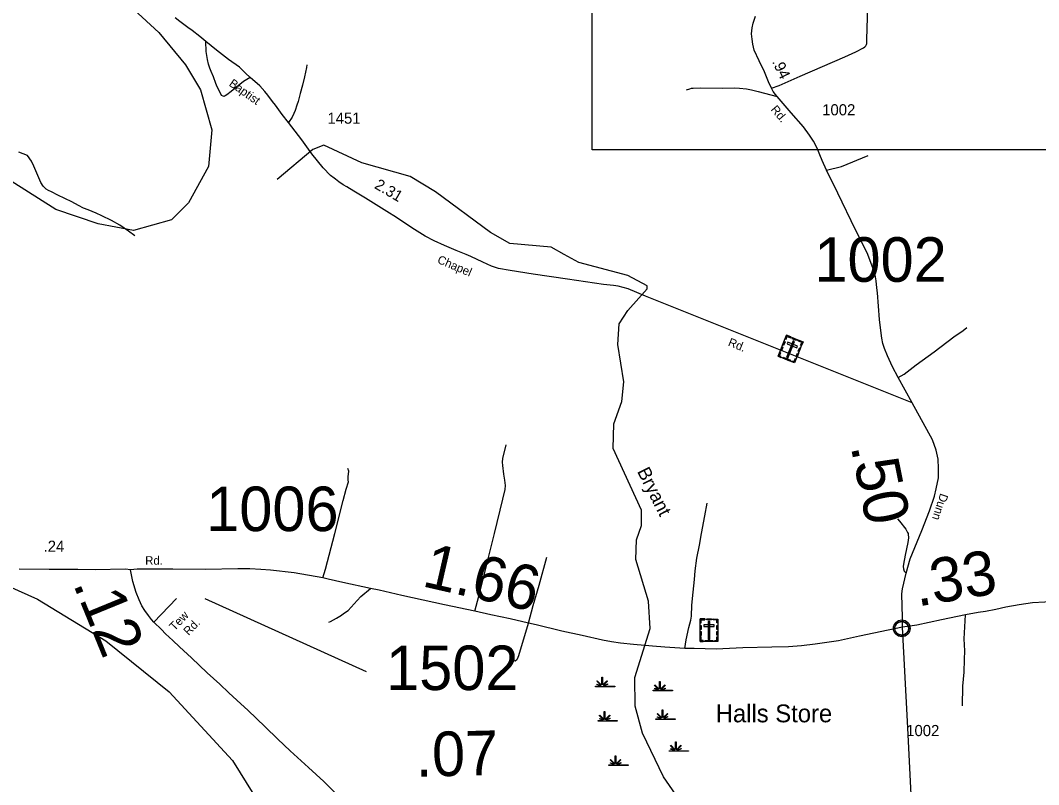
# Model space of a CAD drawing. Extents: x 2093524 to 2270757, y 289120 to 570408.
# Drawn here: x 2128353 to 2139794, y 494834 to 503417 of the extents above; entities that cross this region are included whole.
import ezdxf

# ---------------------------------------------------------------- set-up
doc = ezdxf.new("R2010")
doc.units = 0
for name, color, linetype in [('Exist Civil Demographics Community CELL', 7, 'Continuous'), ('Exist Civil Demographics Community Label', 7, 'Continuous'), ('Exist Cultural Cemetery CELL', 7, 'Continuous'), ('Exist Hydrographic Creek Single Shore', 7, 'Continuous'), ('Exist Hydrographic Misc Water Feature', 7, 'Continuous'), ('Exist Hydrographic Pond Under 1500 Sq Ft', 7, 'Continuous'), ('Exist Hydrographic Swamp CELL', 7, 'Continuous'), ('Exist Hydrographic Swamp Label', 7, 'Continuous'), ('Exist Road Non-System Type 51', 7, 'Continuous'), ('Exist Road Secondary Mileage Hundredths English Label', 7, 'Continuous'), ('Exist Road Secondary Type 51 Attributed', 7, 'Continuous'), ('Exist Road Secondary Type 51 Label', 7, 'Continuous'), ('Exist Road Secondary Type 51 Number Label', 7, 'Continuous'), ('Map Preparation Inset Cut Line', 7, 'Continuous')]:
    doc.layers.add(name, color=color, linetype=linetype)

msp = doc.modelspace()

# ---------------------------------------------------------------- linework, layer by layer
at = {"layer": 'Exist Civil Demographics Community CELL'}
msp.add_lwpolyline([(2138178, 496602), (2138179, 496607), (2138181, 496614), (2138184, 496621), (2138187, 496627), (2138190, 496632), (2138194, 496638), (2138198, 496642), (2138202, 496647), (2138208, 496651), (2138213, 496655), (2138218, 496658), (2138223, 496660), (2138229, 496662), (2138234, 496664), (2138239, 496665), (2138244, 496666), (2138248, 496667), (2138254, 496667), (2138258, 496667), (2138264, 496667), (2138269, 496666), (2138274, 496665), (2138279, 496664), (2138284, 496662), (2138291, 496659), (2138297, 496655), (2138302, 496652), (2138307, 496648), (2138311, 496645), (2138315, 496640), (2138319, 496635), (2138322, 496631), (2138325, 496626), (2138327, 496621), (2138329, 496616), (2138331, 496611), (2138332, 496606), (2138333, 496600), (2138334, 496595), (2138334, 496589), (2138334, 496584), (2138333, 496578), (2138332, 496572), (2138331, 496566), (2138329, 496560), (2138327, 496555), (2138323, 496549), (2138320, 496544), (2138317, 496539), (2138312, 496535), (2138307, 496530), (2138302, 496525), (2138297, 496522), (2138293, 496520), (2138286, 496516), (2138279, 496514), (2138273, 496512), (2138266, 496511), (2138262, 496510), (2138257, 496510), (2138252, 496510), (2138248, 496511), (2138242, 496511), (2138236, 496513), (2138231, 496514), (2138226, 496516), (2138222, 496518), (2138218, 496520), (2138211, 496524), (2138205, 496528), (2138200, 496533), (2138196, 496538), (2138193, 496542), (2138190, 496546), (2138186, 496553), (2138184, 496556), (2138182, 496560), (2138180, 496569), (2138178, 496576), (2138177, 496581), (2138177, 496587), (2138177, 496592), (2138178, 496598)], close=True, dxfattribs=at)
for centre, radius in [((2138256, 496589), 94.3), ((2138255, 496589), 76.7)]:
    msp.add_circle(centre, radius, dxfattribs=at)
at = {"layer": 'Exist Cultural Cemetery CELL'}
for points in [[(2136962, 499880), (2137146, 499806), (2137052, 499570), (2136867, 499644)], [(2136946, 499840), (2136956, 499836), (2136968, 499866), (2137006, 499850), (2137010, 499861), (2136962, 499880)], [(2137030, 499853), (2137079, 499833), (2137074, 499823), (2137026, 499842)], [(2136893, 499709), (2136909, 499749), (2136920, 499745), (2136904, 499704)], [(2136918, 499771), (2136934, 499811), (2136945, 499807), (2136929, 499767)], [(2137052, 499812), (2137035, 499819), (2136959, 499631), (2136977, 499624)], [(2136974, 499802), (2136967, 499784), (2137077, 499741), (2137084, 499758)], [(2137093, 499702), (2137109, 499742), (2137119, 499738), (2137103, 499698)], [(2137130, 499766), (2137120, 499770), (2137132, 499800), (2137094, 499815), (2137098, 499825), (2137147, 499806)], [(2136898, 499631), (2136902, 499642), (2136882, 499650), (2136897, 499688), (2136886, 499692), (2136867, 499644)], [(2136925, 499633), (2137004, 499601), (2136999, 499591), (2136921, 499622)], [(2137021, 499582), (2137026, 499593), (2137046, 499585), (2137061, 499622), (2137071, 499618), (2137052, 499570)], [(2137068, 499641), (2137084, 499681), (2137095, 499677), (2137079, 499637)], [(2135991, 496695), (2136190, 496694), (2136190, 496440), (2135991, 496440)], [(2135991, 496652), (2136002, 496652), (2136002, 496684), (2136043, 496684), (2136043, 496695), (2135991, 496695)], [(2136065, 496695), (2136117, 496695), (2136117, 496683), (2136065, 496683)], [(2136100, 496665), (2136081, 496665), (2136081, 496463), (2136100, 496463)], [(2136190, 496651), (2136179, 496651), (2136179, 496683), (2136138, 496683), (2136138, 496695), (2136190, 496694)], [(2135991, 496577), (2135991, 496621), (2136002, 496621), (2136002, 496577)], [(2135991, 496510), (2135991, 496554), (2136002, 496554), (2136002, 496510)], [(2136032, 496627), (2136032, 496608), (2136149, 496608), (2136149, 496627)], [(2136178, 496512), (2136178, 496555), (2136190, 496555), (2136190, 496512)], [(2136179, 496578), (2136179, 496621), (2136190, 496621), (2136190, 496578)], [(2136024, 496440), (2136024, 496452), (2136002, 496452), (2136002, 496492), (2135991, 496492), (2135990, 496440)], [(2136048, 496452), (2136133, 496451), (2136133, 496440), (2136048, 496440)], [(2136156, 496440), (2136157, 496451), (2136179, 496451), (2136179, 496492), (2136190, 496492), (2136190, 496440)]]:
    msp.add_lwpolyline(points, close=True, dxfattribs=at)
at = {"layer": 'Exist Hydrographic Creek Single Shore'}
msp.add_lwpolyline([(2135847, 494531), (2135579, 494920), (2135343, 495411), (2135259, 495717), (2135257, 496036), (2135430, 496587), (2135412, 496895), (2135268, 497361), (2135276, 497584), (2135333, 497743), (2135333, 497917), (2135013, 498609), (2135020, 498885), (2135111, 499135), (2135135, 499358), (2135066, 499776), (2135082, 500008), (2135180, 500157), (2135397, 500402), (2135397, 500435), (2135180, 500551), (2134628, 500697), (2134462, 500788)], dxfattribs=at)
at = {"layer": 'Exist Hydrographic Misc Water Feature'}
for points in [[(2134462, 500788), (2134318, 500870), (2133852, 500909), (2133635, 501035), (2133016, 501490), (2132732, 501663), (2132189, 501818), (2131763, 502017), (2131638, 501967), (2131240, 501631)], [(2128221, 497062), (2128546, 496915), (2129315, 496450), (2130025, 495878), (2130737, 495106), (2131216, 494335)]]:
    msp.add_lwpolyline(points, dxfattribs=at)
at = {"layer": 'Exist Hydrographic Pond Under 1500 Sq Ft'}
for points in [[(2129626, 501056), (2129226, 501130), (2128751, 501293), (2128249, 501609), (2127923, 501868), (2127429, 502471), (2127370, 502663), (2127193, 503103), (2127167, 503244), (2127208, 503647)], [(2129440, 503714), (2129908, 503281), (2130210, 502918), (2130378, 502635), (2130505, 502187), (2130466, 501777), (2130241, 501369), (2130051, 501176), (2129626, 501056)]]:
    msp.add_lwpolyline(points, dxfattribs=at)
at = {"layer": 'Exist Hydrographic Swamp CELL'}
for points in [[(2134815, 495940), (2134867, 495940), (2134869, 495943), (2134831, 495958), (2134834, 495963), (2134872, 495948), (2134873, 495951), (2134829, 495995), (2134834, 496000), (2134879, 495955), (2134886, 495957), (2134886, 496040), (2134893, 496040), (2134893, 495957), (2134899, 495955), (2134944, 496000), (2134950, 495995), (2134905, 495951), (2134907, 495947), (2134948, 495966), (2134950, 495960), (2134910, 495943), (2134911, 495940), (2135032, 495940), (2135032, 495933), (2134815, 495933)], [(2135464, 495893), (2135516, 495893), (2135518, 495896), (2135480, 495911), (2135483, 495916), (2135521, 495901), (2135522, 495903), (2135478, 495948), (2135483, 495953), (2135528, 495908), (2135535, 495910), (2135535, 495993), (2135542, 495993), (2135542, 495910), (2135548, 495908), (2135594, 495953), (2135599, 495948), (2135554, 495903), (2135556, 495900), (2135597, 495918), (2135600, 495913), (2135559, 495896), (2135560, 495893), (2135681, 495893), (2135681, 495886), (2135464, 495886)], [(2134843, 495554), (2134896, 495554), (2134898, 495558), (2134859, 495572), (2134862, 495578), (2134900, 495562), (2134901, 495565), (2134857, 495609), (2134862, 495614), (2134907, 495569), (2134914, 495571), (2134914, 495654), (2134921, 495654), (2134921, 495571), (2134927, 495569), (2134973, 495614), (2134978, 495609), (2134933, 495565), (2134935, 495561), (2134976, 495580), (2134979, 495575), (2134938, 495557), (2134939, 495554), (2135060, 495554), (2135060, 495547), (2134843, 495547)], [(2135492, 495573), (2135545, 495573), (2135547, 495576), (2135508, 495591), (2135511, 495596), (2135549, 495581), (2135551, 495584), (2135506, 495628), (2135511, 495633), (2135557, 495588), (2135563, 495590), (2135563, 495673), (2135570, 495673), (2135570, 495590), (2135577, 495588), (2135622, 495633), (2135627, 495628), (2135583, 495584), (2135585, 495580), (2135625, 495599), (2135628, 495594), (2135587, 495576), (2135589, 495573), (2135710, 495573), (2135710, 495566), (2135492, 495566)], [(2135643, 495215), (2135695, 495215), (2135697, 495219), (2135659, 495234), (2135662, 495239), (2135700, 495223), (2135701, 495226), (2135657, 495271), (2135662, 495276), (2135707, 495230), (2135713, 495233), (2135713, 495316), (2135721, 495316), (2135721, 495233), (2135727, 495230), (2135772, 495276), (2135777, 495271), (2135733, 495226), (2135735, 495222), (2135776, 495241), (2135778, 495236), (2135737, 495218), (2135739, 495215), (2135860, 495215), (2135860, 495208), (2135643, 495208)], [(2134965, 495055), (2135018, 495055), (2135020, 495059), (2134982, 495074), (2134984, 495079), (2135022, 495063), (2135024, 495066), (2134979, 495111), (2134984, 495116), (2135030, 495070), (2135036, 495073), (2135036, 495156), (2135043, 495156), (2135043, 495073), (2135050, 495070), (2135095, 495116), (2135100, 495111), (2135056, 495066), (2135058, 495063), (2135099, 495081), (2135101, 495076), (2135060, 495058), (2135062, 495055), (2135183, 495055), (2135183, 495048), (2134965, 495048)]]:
    msp.add_lwpolyline(points, close=True, dxfattribs=at)
at = {"layer": 'Exist Road Non-System Type 51'}
for points in [[(2136792, 502654), (2136877, 502684), (2137113, 502791), (2137615, 503007), (2137739, 503063), (2137825, 503107), (2137842, 503119), (2137852, 503130), (2137860, 503144), (2137864, 503156), (2137865, 503202), (2137872, 503448), (2137887, 504092), (2137894, 504427), (2137899, 504597), (2137905, 504671), (2137904, 504713), (2137900, 504743), (2137893, 504795), (2137884, 504832), (2137852, 504902)], [(2130935, 502776), (2130859, 502729), (2130781, 502665), (2130720, 502616), (2130672, 502581), (2130653, 502571), (2130643, 502563), (2130631, 502564), (2130613, 502574), (2130600, 502600), (2130565, 502671), (2130548, 502709), (2130522, 502782), (2130495, 502842), (2130480, 502881), (2130468, 502925), (2130454, 502979), (2130441, 503067), (2130438, 503178)], [(2131572, 502919), (2131566, 502889), (2131544, 502783), (2131524, 502690), (2131498, 502594), (2131474, 502507), (2131461, 502463), (2131442, 502405), (2131427, 502372), (2131406, 502328), (2131365, 502269)], [(2135838, 502635), (2135876, 502646), (2135894, 502654), (2135911, 502656), (2135993, 502658), (2136245, 502657), (2136379, 502658), (2136432, 502657), (2136512, 502649), (2136566, 502638), (2136642, 502619), (2136855, 502563)], [(2129638, 500998), (2129567, 501051), (2129472, 501115), (2129377, 501171), (2129270, 501221), (2129205, 501253), (2129114, 501288), (2129064, 501309), (2129005, 501339), (2128930, 501378), (2128775, 501455), (2128702, 501491), (2128670, 501507), (2128642, 501520), (2128635, 501528), (2128609, 501555), (2128584, 501595), (2128506, 501781), (2128479, 501837), (2128432, 501898), (2128386, 501919), (2128337, 501936)], [(2137412, 501736), (2137579, 501776), (2137877, 501900)], [(2138215, 499405), (2138282, 499444), (2138418, 499547), (2138621, 499695), (2138842, 499861), (2138944, 499935), (2138986, 499968)], [(2133459, 496781), (2133520, 497008), (2133609, 497370), (2133681, 497656), (2133774, 498040), (2133799, 498150), (2133803, 498192), (2133797, 498254), (2133786, 498322), (2133772, 498416), (2133769, 498454), (2133773, 498496), (2133813, 498650)], [(2131753, 497157), (2131781, 497254), (2131885, 497656), (2131978, 498026), (2132013, 498152), (2132040, 498233), (2132035, 498255), (2132035, 498289), (2132043, 498353), (2132033, 498383)], [(2135818, 496362), (2135832, 496461), (2135865, 496597), (2135887, 496680), (2135892, 496726), (2135896, 496848), (2135913, 496994), (2135928, 497137), (2135934, 497235), (2135953, 497379), (2135982, 497524), (2136004, 497654), (2136044, 497851), (2136069, 497996)], [(2138209, 497820), (2138231, 497793), (2138301, 497704), (2138313, 497680), (2138322, 497667), (2138326, 497655), (2138328, 497645), (2138333, 497607), (2138324, 497553), (2138295, 497412), (2138275, 497308), (2138273, 497282), (2138276, 497256), (2138282, 497230), (2138305, 497210)], [(2134062, 496647), (2134116, 496844), (2134181, 497074), (2134269, 497387)], [(2131819, 496658), (2131839, 496667), (2131904, 496704), (2131962, 496737), (2131985, 496754), (2132037, 496789), (2132136, 496903), (2132177, 496947), (2132286, 497038)], [(2133844, 496241), (2133852, 496235), (2133876, 496227), (2133902, 496228), (2133914, 496226), (2133930, 496238), (2133940, 496245), (2133955, 496285), (2134062, 496647)], [(2138937, 495719), (2138942, 495938), (2138956, 496097), (2138959, 496241), (2138965, 496336), (2138958, 496473), (2138973, 496741)]]:
    msp.add_lwpolyline(points, dxfattribs=at)
at = {"layer": 'Exist Road Secondary Type 51 Attributed'}
msp.add_line((2129852, 496658), (2130107, 496926), dxfattribs=at)
for points in [[(2138374, 499122), (2135376, 500320), (2135181, 500400), (2135070, 500430), (2135018, 500441), (2134905, 500451), (2134502, 500509), (2134115, 500565), (2133856, 500606), (2133726, 500629), (2133647, 500657), (2133548, 500701), (2133413, 500765), (2133360, 500787), (2133250, 500833), (2133119, 500890), (2133004, 500942), (2132901, 500994), (2132753, 501087), (2132578, 501201), (2132471, 501269), (2132232, 501420), (2132098, 501498), (2132021, 501546), (2131981, 501569), (2131932, 501604), (2131892, 501634), (2131879, 501645), (2131839, 501676), (2131755, 501761), (2131628, 501918), (2131517, 502074), (2131365, 502269), (2131295, 502358), (2131219, 502466), (2131186, 502507), (2131133, 502576), (2131100, 502618), (2131044, 502681), (2130935, 502776), (2130882, 502825), (2130814, 502890), (2130690, 502979), (2130625, 503030), (2130556, 503083), (2130438, 503178), (2130369, 503237), (2130282, 503301), (2130235, 503338), (2130146, 503403), (2130093, 503444)], [(2138374, 499122), (2138215, 499405), (2138152, 499524), (2138094, 499650), (2138062, 499730), (2138045, 499789), (2138032, 499847), (2138016, 499963), (2138004, 500059), (2137982, 500358), (2137977, 500412), (2137969, 500492), (2137960, 500538), (2137941, 500609), (2137867, 500807), (2137736, 501065), (2137539, 501477), (2137412, 501736), (2137360, 501843), (2137301, 501988), (2137264, 502060), (2137220, 502127), (2137150, 502221), (2137013, 502377), (2136855, 502563), (2136839, 502583), (2136812, 502619), (2136792, 502654), (2136760, 502726), (2136712, 502839), (2136655, 502961), (2136599, 503082), (2136582, 503150), (2136574, 503206), (2136569, 503264), (2136574, 503334), (2136585, 503384), (2136613, 503465)], [(2138264, 496602), (2138264, 496673), (2138261, 496881), (2138258, 496935), (2138257, 496975), (2138266, 497033), (2138305, 497210), (2138352, 497369), (2138481, 497688), (2138567, 497908), (2138624, 498073), (2138644, 498155), (2138667, 498278), (2138669, 498386), (2138663, 498490), (2138643, 498589), (2138601, 498706), (2138374, 499122)], [(2129590, 497247), (2129536, 497252), (2129194, 497248), (2129000, 497249), (2128676, 497250), (2128340, 497252)], [(2138264, 496602), (2137780, 496502), (2137544, 496450), (2137283, 496411), (2137131, 496391), (2136984, 496383), (2136795, 496378), (2136470, 496369), (2136172, 496357), (2135922, 496362), (2135818, 496362), (2135595, 496376), (2135455, 496389), (2135243, 496409), (2135094, 496424), (2134994, 496436), (2134894, 496456), (2134665, 496507), (2134437, 496559), (2134150, 496627), (2134062, 496647), (2133855, 496695), (2133640, 496739), (2133459, 496781), (2133119, 496854), (2132639, 496959), (2132386, 497016), (2132286, 497038), (2131976, 497105), (2131813, 497142), (2131753, 497157), (2131428, 497212), (2131163, 497243), (2131053, 497251), (2130933, 497257), (2130795, 497256), (2130433, 497251), (2130065, 497255), (2129667, 497255), (2129590, 497247)], [(2129852, 496658), (2129825, 496687), (2129791, 496732), (2129750, 496790), (2129717, 496843), (2129687, 496911), (2129654, 496992), (2129616, 497117), (2129590, 497247)], [(2140003, 496891), (2139725, 496874), (2139575, 496852), (2139426, 496827), (2139312, 496802), (2139195, 496777), (2139115, 496766), (2138973, 496741), (2138704, 496683), (2138427, 496625), (2138264, 496602)], [(2131944, 494689), (2131761, 494869), (2131589, 495028), (2131386, 495214), (2131246, 495344), (2131105, 495484), (2130908, 495671), (2130829, 495741), (2130697, 495865), (2130593, 495961), (2130453, 496091), (2130274, 496258), (2130140, 496382), (2130067, 496453), (2129982, 496529), (2129937, 496575), (2129852, 496658)], [(2138384, 494275), (2138322, 495542), (2138264, 496602)]]:
    msp.add_lwpolyline(points, dxfattribs=at)
at = {"layer": 'Exist Road Secondary Type 51 Number Label'}
msp.add_line((2130425, 496926), (2132237, 496103), dxfattribs=at)
at = {"layer": 'Map Preparation Inset Cut Line'}
msp.add_lwpolyline([(2134776, 516144), (2162949, 516144), (2162949, 501961), (2134776, 501961)], close=True, dxfattribs=at)

# ---------------------------------------------------------------- texts
at = {"layer": 'Exist Civil Demographics Community Label'}
msp.add_text('Halls Store', height=200, dxfattribs=at).set_placement((2136166, 495534))
at = {"layer": 'Exist Hydrographic Swamp Label'}
msp.add_text('Bryant', height=150, rotation=296.8861, dxfattribs=at).set_placement((2135279, 498352))
at = {"layer": 'Exist Road Secondary Mileage Hundredths English Label'}
for s, height, rotation, p in [('.94', 125, 295.6397, (2136796, 502953)), ('2.31', 125, 329.6479, (2132322, 501537)), ('.50', 500, 281.4891, (2137681, 498633)), ('.24', 125, 359.8758, (2128614, 497449)), ('1.66', 500, 347.063, (2132853, 497065)), ('.33', 500, 9.4666, (2138432, 496833)), ('.12', 500, 292.2499, (2128941, 497090)), ('.07', 500, 1.3699, (2132798, 494922))]:
    msp.add_text(s, height=height, rotation=rotation, dxfattribs=at).set_placement(p)
at = {"layer": 'Exist Road Secondary Type 51 Label'}
for s, rotation, p in [('Baptist', 324.5275, (2130689, 502689)), ('Rd.', 310.5223, (2136778, 502412)), ('Chapel', 337.1051, (2133030, 500695)), ('Rd.', 338.218, (2136297, 499766)), ('Dunn', 251.8896, (2138690, 498111)), ('Rd.', 0.0146, (2129756, 497304)), ('Tew', 45.8738, (2130085, 496555)), ('Rd.', 45.8738, (2130243, 496503))]:
    msp.add_text(s, height=95, rotation=rotation, dxfattribs=at).set_placement(p)
at = {"layer": 'Exist Road Secondary Type 51 Number Label'}
for s, height, p in [('1002', 125, (2137362, 502350)), ('1451', 125, (2131803, 502256)), ('1002', 500, (2137274, 500481)), ('1006', 500, (2130441, 497681)), ('1502', 500, (2132462, 495896)), ('1002', 125, (2138306, 495379))]:
    msp.add_text(s, height=height, dxfattribs=at).set_placement(p)

doc.saveas('drawing.dxf')
